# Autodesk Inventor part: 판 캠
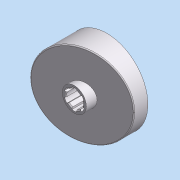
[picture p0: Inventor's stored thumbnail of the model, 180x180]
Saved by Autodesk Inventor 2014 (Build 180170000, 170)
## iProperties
Created: 2012-05
Part Number: 판 캠
Document SubType Name: 모델링
Designer: SeoGD™
Material: 강철
Appearance: 알루미늄 - 평지
Mass: 86.8264 g
Surface Area: 331.303 cm^2
Volume: 86.8264 cm^3
Density: 1 g/cm^3
변환 표준: STEP AP214IS
파일 이름: C:\Users\SeoGD\Desktop\?쒗뿕\??stp
전처리기: Build: 253, Release: 2010 SP1 - Date: Wed 07/29/2009
전송 단위: 밀리미터
불확실성: 0.01
Author: SeoGD™
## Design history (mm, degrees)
node "작업 평면4"
sketch "스케치1"
  geometry: C1 r 44.5 at (0, 0); 1 further point
  constraints: 1 centre point, 1 coincident
  dimensions: "d25" = 89 diameter of C1
extrude "돌출1" new body sketch "스케치1" distance "d1" = 40; taper "d2" = 0 deg
sketch "스케치2"
  geometry: L1 (-44.5, 15)-(44.5, 38.847); L2 (-44.5, 0)-(-44.5, 40) reference; L3 (-44.5, 40)-(44.5, 40) reference; L4 (44.5, 0)-(44.5, 40) reference; 1 further point
  constraints: 2 end point, 2 point on line
  dimensions: "d26" = 15 distance of L2.start L1.start; "d27" = 75 deg angle of L1 L2
extrude "돌출2" cut sketch "스케치2" stored distance "d5" = 40; taper "d6" = 0 deg
node "작업 평면1"
sketch "스케치3"
  geometry: C1 r 13 at (0, 0); 1 further point
  constraints: 1 centre point, 1 coincident
  dimensions: "d9" = 26 diameter of C1
extrude "돌출3" join sketch "스케치3" distance "d10" = 38; taper "d11" = 0 deg
hole "구멍1" diameter "d14" = 18; stored, may be unused: countersink angle "d18" = 90 deg, drill point angle "d20" = 118 deg; dims "d12" = 10, "d13" = 10, "d15" = 6, "d16" = 4, "d17" = 2, "d19" = 8
feature "쉘2" dims "d29" = 5
sketch "스케치6"
  geometry: C1 r 17.5 at (0, 0); C2 r 14 at (0, 0) reference; 1 further point
  constraints: 1 centre point, 1 coincident
  dimensions: "d28" = 35 diameter of C1
extrude "돌출4" join sketch "스케치6" stored distance "d30" = 38; taper "d31" = 0 deg
fillet "모깎기1" dims "d32" = 3
chamfer "모따기1" distance "d21" = 1; stored, may be unused: second distance "d22" = 2, angle "d23" = 45 deg
sketch "스케치7"
  geometry: L1 (-12.374, 12.374)-(-27.931, 27.931); A1 r 39.5 centre (0, 0) between (-27.931, 27.931) and (0, 39.5) reference; 2 further points
  constraints: 2 end point, 2 point on circle, 1 point on line, 1 vertical alignment, 2 other
  dimensions: "d33" = 45 deg dimension on point (0, 0) L1.start A1.end
feature "리브1" sketch "스케치7" dims "d34" = 5, "d35" = 1, "d36" = 0
fillet "모깎기2" dims "d37" = 3
sketch "스케치8"
  geometry: L1 (2.5, 10.712)-(2.5, 8.646); L2 (-2.5, 10.712)-(-2.5, 8.646); A1 r 11 centre (0, 0) between (2.5, 10.712) and (-2.5, 10.712); A2 r 9 centre (0, 0) between (2.5, 8.646) and (-2.5, 8.646) reference; 1 further point
  constraints: 4 end point, 4 point on circle, 2 parallel, 1 centre point, 1 coincident, 1 vertical
  dimensions: "d41" = 22 diameter of A1; "d42" = 5 distance between parallel lines of L1 L2
extrude "돌출5" cut sketch "스케치8" stored distance "d43" = 38; taper "d44" = 0 deg
fillet "모깎기3" dims "d48" = 1
node "솔리드1"
node "솔리드 본체"
node "곡면 본체"
pattern_circular "원형 패턴1" dims angle "d39" = 360 deg
pattern_circular "원형 패턴2" dims angle "d46" = 360 deg
node "솔리드2"
